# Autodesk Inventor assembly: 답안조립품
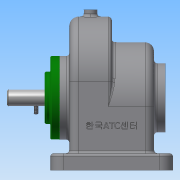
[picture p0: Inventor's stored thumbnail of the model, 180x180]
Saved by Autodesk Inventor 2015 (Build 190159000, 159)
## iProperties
Created: 2017-11
Part Number: 답안조립품
Document SubType Name: Assembly
Designer: user
Author: user
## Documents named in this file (13)
- C:\Users\user\Desktop\471107v1004\답안조립품.iam
- C:\Users\user\Desktop\471107v1004\1본체.ipt
- C:\Users\user\Desktop\471107v1004\축.ipt
- C:\Users\user\Desktop\471107v1004\베어링 6002.ipt
- C:\Users\user\Desktop\471107v1004\키 - 6 x 6 x 22.ipt
- C:\Users\user\Desktop\471107v1004\스퍼기어.ipt
- C:\Users\user\Desktop\471107v1004\V-벨트풀리.ipt
- C:\Users\user\Desktop\471107v1004\키 - 5 x 5 x 18.ipt
- C:\Users\user\Desktop\471107v1004\앞커버.ipt
- C:\Users\user\Desktop\471107v1004\오일 실 15 30 7.ipt
- C:\Users\user\Desktop\471107v1004\멈춤나사 - M4 x 10.ipt
- 멈춤나사 - M4 x 10.ipt
- C:\Users\user\Desktop\471107v1004\볼트 M3 x 8.ipt
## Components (2 placed, 2 different names)
1. 1본체:1
2. V-벨트풀리:2
